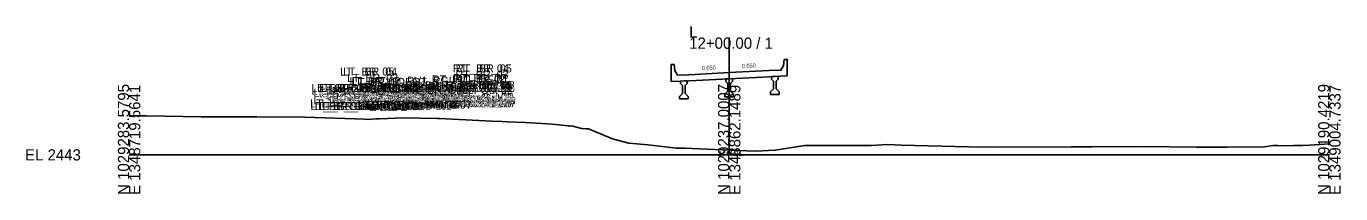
# Model space of a CAD drawing. Extents: x -26 to 1453, y -10 to 4527.
# Drawn here: x -25.7 to 302.8, y 1990.3 to 2032.1 of the extents above; entities that cross this region are included whole.
import ezdxf

# ---------------------------------------------------------------- set-up
doc = ezdxf.new("R2010")
doc.units = 0
for name, color, linetype in [('Default', 7, 'Continuous'), ('Exist Cross Section Cell', 7, 'Continuous'), ('Exist XS Center Line Elevation Label', 7, 'Continuous'), ('Exist XS Ground Line', 7, 'Continuous'), ('Prop CMT Concrete Structures', 7, 'Continuous'), ('Prop XS SE Text', 7, 'Continuous')]:
    doc.layers.add(name, color=color, linetype=linetype)

msp = doc.modelspace()

# ---------------------------------------------------------------- linework, layer by layer
at = {"layer": 'Exist Cross Section Cell'}
for p, q in [((150, 2000), (150, 2029.29)), ((0, 2000), (150, 2000)), ((150, 2000), (300, 2000))]:
    msp.add_line(p, q, dxfattribs=at)
at = {"layer": 'Exist XS Ground Line'}
msp.add_lwpolyline([(0, 2009.76), (4.32, 2009.72), (13.42, 2009.61), (18.04, 2009.53), (29.48, 2009.51), (31.92, 2009.51), (43.98, 2009.38), (58.91, 2008.88), (60.12, 2008.86), (60.62, 2008.91), (61.79, 2009.02), (62.58, 2008.98), (68.6, 2009.25), (76.88, 2009.1), (77.72, 2009.06), (79.27, 2008.97), (90.63, 2008.37), (93.13, 2008.29), (94.56, 2008.22), (99.02, 2008.05), (104.47, 2007.74), (105.76, 2007.68), (109.83, 2007.27), (110.06, 2007.2), (110.55, 2007.22), (113.09, 2006.62), (114.16, 2006.49), (114.82, 2006.53), (120.8, 2004.04), (124.9, 2002.89), (129.72, 2002.48), (136.79, 2001.69), (138.89, 2001.68), (150, 2001.21), (156.56, 2000.94), (161.48, 2001.19), (168.87, 2002.35), (185.52, 2002.37), (189.68, 2002.59), (193.1, 2002.42), (209.77, 2001.97), (216.32, 2001.96), (235.56, 2002.03), (240.69, 2002.02), (253.28, 2002.08), (266.72, 2001.93), (273.63, 2001.95), (274.43, 2001.95), (283.79, 2001.97), (285.97, 2002.32), (287.01, 2002.3), (287.83, 2002.29), (291.13, 2002.32), (293.19, 2002.36), (295, 2002.4), (300, 2002.79)], dxfattribs=at)
at = {"layer": 'Prop CMT Concrete Structures'}
for points in [[(150, 2020.52), (160, 2021.02), (163, 2021.17), (163.01, 2021.42), (163.59, 2022.25), (163.76, 2023.83), (164.5, 2023.83), (164.5, 2019.74)], [(150, 2020.52), (140, 2020.02), (137, 2019.87), (136.99, 2020.12), (136.41, 2020.95), (136.24, 2022.53), (135.5, 2022.53), (135.5, 2018.29)], [(150, 2019.02), (150, 2020.52)], [(150, 2019.02), (150, 2020.52)], [(135.5, 2018.29), (140, 2018.52), (150, 2019.02)], [(139.46, 2018.49), (138.62, 2018.45), (137.79, 2018.41)], [(137.79, 2018.41), (137.79, 2017.78)], [(137.79, 2017.78), (138.29, 2017.28)], [(138.29, 2017.28), (138.29, 2015.36)], [(138.96, 2017.28), (139.46, 2017.78)], [(138.96, 2015.36), (138.96, 2017.28)], [(139.46, 2017.78), (139.46, 2018.49)], [(150, 2019.02), (149.17, 2018.97)], [(149.17, 2018.97), (149.17, 2018.35)], [(149.17, 2018.35), (149.67, 2017.85)], [(149.67, 2017.85), (149.67, 2015.93)], [(164.5, 2019.74), (160, 2019.52), (150, 2019.02)], [(150, 2019.02), (150.83, 2019.06)], [(150, 2014.52), (150, 2019.02)], [(150, 2014.52), (150, 2019.02)], [(150.83, 2018.35), (150.33, 2017.85)], [(150.33, 2017.85), (150.33, 2015.93)], [(150.83, 2019.06), (150.83, 2018.35)], [(160.54, 2019.54), (161.38, 2019.58), (162.21, 2019.63)], [(160.54, 2018.92), (160.54, 2019.54)], [(161.04, 2018.42), (160.54, 2018.92)], [(161.04, 2016.5), (161.04, 2018.42)], [(162.21, 2018.92), (161.71, 2018.42)], [(161.71, 2018.42), (161.71, 2016.5)], [(162.21, 2019.63), (162.21, 2018.92)], [(138.29, 2015.36), (137.54, 2014.61)], [(137.54, 2014.61), (137.54, 2013.95)], [(137.54, 2013.95), (138.62, 2013.95), (139.71, 2013.95)], [(139.71, 2014.61), (138.96, 2015.36)], [(139.71, 2013.95), (139.71, 2014.61)], [(149.67, 2015.93), (148.92, 2015.18)], [(148.92, 2015.18), (148.92, 2014.52)], [(148.92, 2014.52), (150, 2014.52)], [(151.08, 2014.52), (150, 2014.52)], [(150.33, 2015.93), (151.08, 2015.18)], [(151.08, 2015.18), (151.08, 2014.52)], [(160.29, 2015.75), (161.04, 2016.5)], [(160.29, 2015.08), (160.29, 2015.75)], [(162.46, 2015.08), (161.38, 2015.08), (160.29, 2015.08)], [(161.71, 2016.5), (162.46, 2015.75)], [(162.46, 2015.75), (162.46, 2015.08)]]:
    msp.add_lwpolyline(points, dxfattribs=at)

# ---------------------------------------------------------------- texts
at = {"layer": 'Default'}
for s, height, p in [('LT_ BR_05', 2, (52.74, 2019.8)), ('LT_ BR_04', 2, (53.48, 2019.8)), ('RT_ BR_04', 2, (80.95, 2020.58)), ('RT_BR_03', 2, (81.6, 2019)), ('RT_ BR_05', 2, (81.69, 2020.58)), ('LT_BR_Girder Out 02', 2, (45.58, 2015.66)), ('LT_BR_Girder Out 01', 2, (46.98, 2015.68)), ('LT_BR_Girder Out 14', 2, (47.89, 2015.71)), ('LT_BR_06', 2, (53.51, 2015.59)), ('LT_BR_03', 2, (54.46, 2018.22)), ('LT_BR_02', 2, (55.05, 2017.38)), ('LT_BR_01', 2, (55.62, 2017.13)), ('LT_PV1_OEOT', 2, (55.74, 2017.22)), ('LT_BR_Girder Mid 02', 2, (57.35, 2016)), ('LT_BR_Girder Mid 03', 2, (57.35, 2015.36)), ('LT_BR_07', 2, (58.06, 2015.72)), ('RT_BR_Girder Mid 02', 2, (58.97, 2016.05)), ('RT_BR_Girder Mid 03', 2, (58.97, 2015.36)), ('RT_BR_Girder Out 14', 2, (68.93, 2016.34)), ('RT_BR_Girder Out 13', 2, (68.93, 2015.7)), ('RT_BR_Girder Out 12', 2, (69.43, 2015.2)), ('RT_BR_Girder Out 04', 2, (69.45, 2015.2)), ('PV1_PGL', 2, (69.47, 2017.52)), ('RT_BR_Girder Out 01', 2, (69.68, 2016.36)), ('BR_PGL', 2, (69.83, 2016.02)), ('RT_BR_Girder Out 02', 2, (69.95, 2016.39)), ('RT_BR_Girder Out 03', 2, (69.95, 2015.7)), ('RT_PV1_OEOT', 2, (75.69, 2017.82)), ('RT_BR_07', 2, (78.01, 2016.32)), ('RT_BR_02', 2, (81.02, 2018.16)), ('RT_BR_01', 2, (81.57, 2017.91)), ('RT_BR_06', 2, (82.46, 2016.46)), ('LT_BR_Girder Out 06', 2, (45.28, 2011.85)), ('LT_BR_Girder Out 03', 2, (45.58, 2015.01)), ('LT_BR_Girder Out 04', 2, (46.08, 2014.51)), ('LT_BR_Girder Out 05', 2, (46.08, 2012.6)), ('LT_BR_Girder Out 12', 2, (47.39, 2014.51)), ('LT_BR_Girder Out 13', 2, (47.89, 2015.01)), ('LT_BR_Girder Out 11', 2, (47.96, 2012.6)), ('LT_BR_Girder Out 10', 2, (48.06, 2011.85)), ('LT_BR_Girder Mid 06', 2, (57.05, 2012.19)), ('LT_BR_Girder Mid 04', 2, (57.85, 2014.86)), ('LT_BR_Girder Mid 05', 2, (57.85, 2012.94)), ('RT_BR_Girder Mid 04', 2, (58.47, 2014.86)), ('RT_BR_Girder Mid 05', 2, (58.47, 2012.94)), ('RT_BR_Girder Mid 06', 2, (59.17, 2012.19)), ('RT_BR_Girder Out 09', 2, (68.03, 2011.86)), ('RT_BR_Girder Out 10', 2, (68.6, 2012.53)), ('RT_BR_Girder Out 08', 2, (69.12, 2011.86)), ('RT_BR_Girder Out 05', 2, (69.45, 2013.28)), ('RT_BR_Girder Out 11', 2, (70, 2013.28)), ('RT_BR_Girder Out 06', 2, (70.15, 2012.53)), ('RT_BR_Girder Out 07', 2, (70.2, 2011.86)), ('LT_BR_Girder Out 07', 2, (45.33, 2011.18)), ('LT_BR_Girder Out 08', 2, (46.41, 2011.18)), ('LT_BR_Girder Out 09', 2, (47.49, 2011.18)), ('LT_BR_Girder Mid 07', 2, (57.1, 2011.52)), ('RT_BR_Girder Mid 07', 2, (59.22, 2011.52)), ('BR_Girder Mid 08', 2, (60.87, 2011.52)), ('-', 0.0001, (0, 2000)), ('-', 0.0001, (0, 2000)), ('-', 0.0001, (0, 2000)), ('-', 0.0001, (0, 2000))]:
    msp.add_text(s, height=height, dxfattribs=at).set_placement(p)
at = {"layer": 'Exist Cross Section Cell'}
for s, p in [('L', (140, 2029.29)), ('12+00.00 / 1', (140, 2026.49)), ('EL 2443', (-26, 1998.6))]:
    msp.add_text(s, height=2.8, dxfattribs=at).set_placement(p)
for s, p in [('N 1029283.5795', (0, 1990)), ('E 1348719.5641', (2.8, 1990)), ('N 1029237.0007', (150, 1990)), ('E 1348862.1489', (152.8, 1990)), ('N 1029190.4219', (300, 1990)), ('E 1349004.7337', (302.8, 1990))]:
    msp.add_text(s, height=2.8, rotation=90, dxfattribs=at).set_placement(p)
at = {"layer": 'Exist XS Center Line Elevation Label'}
msp.add_text('2444.21', height=1.23, dxfattribs=at).set_placement((147.11, 1999.71))
at = {"layer": 'Prop XS SE Text'}
for p in [(143.2, 2021.18), (153.2, 2021.68)]:
    msp.add_text('0.050', height=1, rotation=2.8624, dxfattribs=at).set_placement(p)

doc.saveas('drawing.dxf')
